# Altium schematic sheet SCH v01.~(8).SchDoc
size A3; SheetNumber: 1; SheetTotal: 1
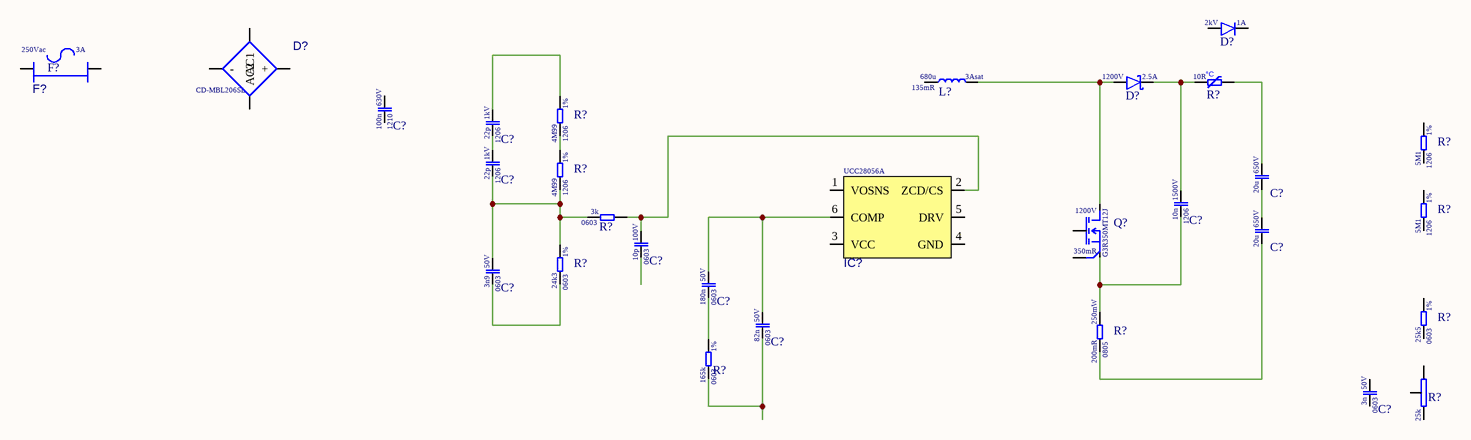
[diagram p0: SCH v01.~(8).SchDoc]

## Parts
(Parts that share a designator on the sheet are numbered #1, #2 ... from top to bottom, then left to right.)
C?#1  Voltage Rating: 630V  Case Code (Imperial): 1210  Capacitance: 100n  [CAP_1210]  (hidden comment: Generic Capacitor model)
C?#2  Voltage Rating: 1kV  Case Code (Imperial): 1206  Capacitance: 22p  [Cap_1206]  (hidden comment: Generic Capacitor model)
C?#3  Voltage Rating: 1kV  Case Code (Imperial): 1206  Capacitance: 22p  [Cap_1206]  (hidden comment: Generic Capacitor model)
C?#4  Voltage Rating: 650V  Capacitance: 20u  [C4AQCBW5200A3FJ]  (hidden comment: Generic Capacitor model)
C?#5  Voltage Rating: 1500V  Case Code (Imperial): 1206  Capacitance: 10n  [Cap_1206]  (hidden comment: Generic Capacitor model)
C?#6  Voltage Rating: 650V  Capacitance: 20u  [C4AQCBW5200A3FJ]  (hidden comment: Generic Capacitor model)
C?#7  Voltage Rating: 100V  Case Code (Imperial): 0603  Capacitance: 10p  [CAP 0603]  (hidden comment: Generic Capacitor model)
C?#8  Voltage Rating: 50V  Case Code (Imperial): 0603  Capacitance: 3n9  [CAP 0603]  (hidden comment: Generic Capacitor model)
C?#9  Voltage Rating: 50V  Case Code (Imperial): 0603  Capacitance: 180n  [CAP 0603]  (hidden comment: Generic Capacitor model)
C?#10  Voltage Rating: 50V  Case Code (Imperial): 0603  Capacitance: 82n  [CAP 0603]  (hidden comment: Generic Capacitor model)
C?#11  Voltage Rating: 50V  Case Code (Imperial): 0603  Capacitance: 3n  [CAP 0603]  (hidden comment: Generic Capacitor model)
D?#1  Forward Current: 1A  Reverse Voltage: 2kV  [SOD-123FL]  (hidden comment: Diode)
D?#2  CD-MBL206SL  [CD-MBL206SL]
D?#3  Forward Current: 2.5A  Reverse Voltage: 1200V  [DO-214-2]  (hidden comment: Diode Schottky)
F?#1  Voltage: 250Vac  Hold Current: 3A  (hidden comment: Fuse no FP)  (graphical)
F?#2  64600001003  [64600001003]  (value not drawn)
IC?  UCC28056A  [SOT-23-6]
L?  Resistance: 135mR  Saturation current: 3Asat  Inductance: 680u  [60B684C]  (hidden comment: Inductor)
Q?  Manufacturer Part Number: G3R350MT12J  Rds: 350mR  Voltage: 1200V  [TO-263-7 D2PAK]  (hidden comment: Nmos_KS)
R?#1  Resistance: 10R  [ICL101D05MIB]  (hidden comment: NTC 10R 1A)
R?#2  Resistance Tolerance: 1%  Resistance: 4M99  Case Code (Imperial): 1206  [RES_1206]  (hidden comment: Generic resistor model)
R?#3  Resistance Tolerance: 1%  Resistance: 5M1  Case Code (Imperial): 1206  [RES_1206]  (hidden comment: Generic resistor model)
R?#4  Resistance Tolerance: 1%  Resistance: 4M99  Case Code (Imperial): 1206  [RES_1206]  (hidden comment: Generic resistor model)
R?#5  Resistance: 3k  Case Code (Imperial): 0603  [RES_0603]  (hidden comment: Generic resistor model)
R?#6  Resistance Tolerance: 1%  Resistance: 5M1  Case Code (Imperial): 1206  [RES_1206]  (hidden comment: Generic resistor model)
R?#7  Resistance Tolerance: 1%  Resistance: 24k3  Case Code (Imperial): 0603  [RES_0603]  (hidden comment: Generic resistor model)
R?#8  Resistance Tolerance: 1%  Resistance: 25k5  Case Code (Imperial): 0603  [RES_0603]  (hidden comment: Generic resistor model)
R?#9  Resistance: 200mR  Power Rating: 250mW  Case Code (Imperial): 0805  [Res_0805]  (hidden comment: Generic resistor model)
R?#10  Resistance Tolerance: 1%  Resistance: 165k  Case Code (Imperial): 0603  [RES_0603]  (hidden comment: Generic resistor model)
R?#11  Resistance: 25k  [RES-67WR10KLF]  (hidden comment: 67WR25KLF)

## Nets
NetC?#2_1: C?#2.1 C?#3.2
NetC?#2_2: C?#2.2 R?#2.2
NetC?#3_1: C?#3.1 C?#8.2 R?#4.1 R?#5.1 R?#7.2
NetC?#4_1: C?#4.1 C?#6.2
NetC?#4_2: C?#4.2 R?#1.2
NetC?#5_1: C?#5.1 Q?.S R?#9.2
NetC?#5_2: C?#5.2 D?#3.K R?#1.1
NetC?#6_1: C?#6.1 R?#9.1
NetC?#7_2: C?#7.2 IC?.2(ZCD/CS) R?#5.2
NetC?#8_1: C?#8.1 R?#7.1
NetC?#9_1: C?#9.1 R?#10.2
NetC?#9_2: C?#9.2 C?#10.2 IC?.6(COMP)
NetC?#10_1: C?#10.1 R?#10.1
NetD?#3_A: D?#3.A L?.2 Q?.D
NetR?#2_1: R?#2.1 R?#4.2

Not connected (* = marked no-connect by the designer): C?#1 1 2; C?#7 1; C?#11 1 2; D?#1 A K; D?#2 + - AC1 AC2; F?#2 1 2; IC? 1(VOSNS) 3(VCC) 4(GND) 5(DRV); L? 1; Q? G KS; R?#3 1 2; R?#6 1 2; R?#8 1 2; R?#11 1 2 3

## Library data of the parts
C?#1 = Cap: Manufacturer: Kemet; Manufacturer Part Number: C1210C104KBRACAUTO
C?#2 C?#3 = Cap: Manufacturer: Walsin; Manufacturer Part Number: 1206N220J102CT
C?#4 C?#6 = Cap: Manufacturer: Kemet
C?#5 = Cap: Manufacturer: Kemet; Manufacturer Part Number: C1206C103KFRACTU
C?#7 = Cap: Manufacturer: Kemet; Manufacturer Part Number: C0603C100J1GAC
C?#8 = Cap: Manufacturer: Vishay; Manufacturer Part Number: VJ0603Y392KXACW1BC
C?#9 = Cap: Manufacturer: Murata; Manufacturer Part Number: GCJ188R91H184KA01D
C?#10 = Cap: Manufacturer: Murata; Manufacturer Part Number: GCM188L81H823KA57D
C?#11 = Cap: Manufacturer: Murata; Manufacturer Part Number: GRM1885C1H302JA01D
D?#1 = Diode: General Diode symbol; Manufacturer: MCC; Manufacturer Part Number: GS1Z-LTP
D?#2 = CD-MBL206SL: Diode Bridge 600V 2A; Manufacturer: Bourns
D?#3 = Diode Schottky: General Schottky Diode symbol; Manufacturer: GenerSiC; Manufacturer Part Number: GB01SLT12-214
F?#1 = Fuse no FP: Generic fuse symbol - no FP; Manufacturer: Littlefuse; Manufacturer Part Number: 06173.15MXP
F?#2 = 64600001003: Fuse Holder 5X20MM 250V 6.3A; Manufacturer: Littlefuse
IC? = UCC28056A: PFC TM IC; Manufacturer: Texas Instruments
L? = Inductor: Generic Inductor symbol; Manufacturer: Murata
Q? = Nmos_KS: Generic Nmos symbol with Kelvin Source; Manufacturer: GeneSiC
R?#1 = ICL101D05MIB: NTC 10R 1A 5mm THT; Manufacturer: Eaton
R?#2 R?#4 = Res: Manufacturer: ROHM; Manufacturer Part Number: KTR18EZPF4994
R?#3 R?#6 = Res: Manufacturer: ROHM; Manufacturer Part Number: KTR18EZPF5104
R?#5 = Res: Manufacturer: Yageo; Manufacturer Part Number: AC0603JR-073KL
R?#7 = Res: Manufacturer: Vishay; Manufacturer Part Number: CRCW060324K3FKEB
R?#8 = Res: Manufacturer: Yageo; Manufacturer Part Number: RT0603DRE0725K5L
R?#9 = Res: Manufacturer: Eaton; Manufacturer Part Number: MFLA0805R2000FA
R?#10 = Res: Manufacturer: Panasonic; Manufacturer Part Number: ERJ-3EKF1653V
R?#11 = 67WR25KLF: Trimpot, 25 kohm, Through Hole, 20 Turns, Multi Turn, Cermet, Top Adjust,; Manufacturer: BI Technologies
